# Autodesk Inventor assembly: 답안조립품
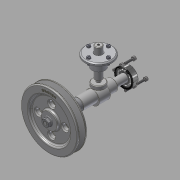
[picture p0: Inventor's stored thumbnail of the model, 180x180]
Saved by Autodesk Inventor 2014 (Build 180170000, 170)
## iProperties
Created: 2015-10
Part Number: 답안조립품
Document SubType Name: Assembly
Designer: youjin14
Author: youjin14
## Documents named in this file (19)
- C:\Users\youjin14\Desktop\451010V1007\답안조립품.iam
- C:\Users\youjin14\Desktop\451010V1007\본체.ipt
- C:\Users\youjin14\Desktop\451010V1007\앞커버.ipt
- C:\Users\youjin14\Desktop\451010V1007\볼트 M4 x 16.ipt
- C:\Users\youjin14\Desktop\451010V1007\뒤커버.ipt
- C:\Users\youjin14\Desktop\451010V1007\상부커버.ipt
- C:\Users\youjin14\Desktop\451010V1007\볼트 M 4 x 12.ipt
- C:\Users\youjin14\Desktop\451010V1007\오일실 15 30 7.ipt
- C:\Users\youjin14\Desktop\451010V1007\베어링- 6202.ipt
- KS B 2023 - 6202 - 15 x 35 x 11 - 7.8.ipt
- C:\Users\youjin14\Desktop\451010V1007\멈춤링- 15 x 1.ipt
- C:\Users\youjin14\Desktop\451010V1007\부시.ipt
- C:\Users\youjin14\Desktop\451010V1007\편심축.ipt
- C:\Users\youjin14\Desktop\451010V1007\슬라이드.ipt
- C:\Users\youjin14\Desktop\451010V1007\멈춤링- 35x1.6.ipt
- KS B 1336 - 35x1.6.ipt
- C:\Users\youjin14\Desktop\451010V1007\키 4 x 4 x 12.ipt
- C:\Users\youjin14\Desktop\451010V1007\V-벨트풀리.ipt
- C:\Users\youjin14\Desktop\451010V1007\너트 M8.ipt
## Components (16 placed, 5 different names)
1. KS B 2023 - 6202 - 15 x 35 x 11 - 7.8:1 — Mate:12, Mate:13, Mate:16, Mate:17, Angle:2
2. KS B 2023 - 6202 - 15 x 35 x 11 - 7.8:2 — Mate:14, Mate:15, Angle:1
3. KS B 1336 - 35x1.6:1 — Mate:23, Mate:24
4. V-벨트풀리:1 — Mate:28, Mate:29, Mate:30, Mate:31
5. ISO 4762 M4 x 16:1 — Insert:1
6. ISO 4762 M4 x 16:2
7. ISO 4762 M4 x 16:3
8. ISO 4762 M4 x 16:4
9. ISO 4762 M4 x 16:5 — Insert:2
10. ISO 4762 M4 x 16:6
11. ISO 4762 M4 x 16:7
12. ISO 4762 M4 x 16:8
13. KS B 1021 - 에 따름 ISO 1207 - 미터 A  M 4 x 12:1 — Insert:3
14. KS B 1021 - 에 따름 ISO 1207 - 미터 A  M 4 x 12:2
15. KS B 1021 - 에 따름 ISO 1207 - 미터 A  M 4 x 12:3
16. KS B 1021 - 에 따름 ISO 1207 - 미터 A  M 4 x 12:4
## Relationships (17: Mate 12, Insert 3, Angle 2)
- Insert:1: ISO 4762 M4 x 16:1
- Insert:2: ISO 4762 M4 x 16:5
- Insert:3: KS B 1021 - 에 따름 ISO 1207 - 미터 A  M 4 x 12:1
- Mate:12: KS B 2023 - 6202 - 15 x 35 x 11 - 7.8:1
- Mate:13: KS B 2023 - 6202 - 15 x 35 x 11 - 7.8:1
- Mate:14: KS B 2023 - 6202 - 15 x 35 x 11 - 7.8:2
- Mate:15: KS B 2023 - 6202 - 15 x 35 x 11 - 7.8:2
- Mate:16: KS B 2023 - 6202 - 15 x 35 x 11 - 7.8:1
- Mate:17: KS B 2023 - 6202 - 15 x 35 x 11 - 7.8:1
- Angle:1: KS B 2023 - 6202 - 15 x 35 x 11 - 7.8:2
- Angle:2: KS B 2023 - 6202 - 15 x 35 x 11 - 7.8:1
- Mate:23: KS B 1336 - 35x1.6:1
- Mate:24: KS B 1336 - 35x1.6:1
- Mate:28: V-벨트풀리:1
- Mate:29: V-벨트풀리:1
- Mate:30: V-벨트풀리:1
- Mate:31: V-벨트풀리:1
